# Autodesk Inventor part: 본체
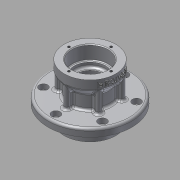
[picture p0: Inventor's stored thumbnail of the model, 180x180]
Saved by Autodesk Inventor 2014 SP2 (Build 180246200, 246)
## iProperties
Created: 2024-04
Part Number: 본체
Material: 알루미늄 6061
Document SubType Name: Modeling
Designer: Administrator
Density: 2.71 g/cm^3
Appearance: 알루미늄 - 평지
Mass: 492.903 g
Surface Area: 449.917 cm^2
Volume: 181.883 cm^3
Author: Administrator
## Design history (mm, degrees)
sketch "스케치1"
  geometry: L1 (-76.3, 0)-(76.3, 0) reference; L2 (0, -76.3)-(0, 76.3) reference; C1 r 54.5 at (0, 0); 1 further point
  constraints: 1 centre point, 1 coincident
  dimensions: "d0" = 109 diameter of C1
extrude "돌출1" new body sketch "스케치1" distance "d1" = 10; taper "d2" = 0 deg
sketch "스케치2"
  geometry: C1 r 54.5 at (0, 0) reference; C2 r 38.5 at (0, 0)
  constraints: 1 centre point, 1 coincident
  dimensions: "d3" = 77 diameter of C2
extrude "돌출2" join sketch "스케치2" distance "d4" = 5; taper "d5" = 0 deg
sketch "스케치3"
  geometry: C1 r 38.5 at (0, 0) reference; C2 r 33.5 at (0, 0)
  constraints: 1 centre point, 1 coincident
  dimensions: "d6" = 67 diameter of C2
extrude "돌출3" join sketch "스케치3" distance "d7" = 15; taper "d8" = 0 deg
node "작업 평면1"
sketch "스케치8"
  geometry: L1 (0, 0)-(0, 72.039); L2 (54.5, 10)-(-54.5, 10) reference; L3 (25.5, 10)-(25.5, 28.121); L4 (25.5, 28.121)-(33.5, 38); L5 (33.5, 38)-(33.5, 50); L6 (33.5, 50)-(0, 50); L7 (25.5, 10)-(0, 10); L8 (0, 50)-(0, 10)
  constraints: 14 end point, 2 perpendicular, 2 point on line, 1 collinear, 1 midpoint, 1 parallel, 1 vertical
  dimensions: "d21" = 67 diameter of L5.end L1; "d22" = 12 distance of L4.end L5.end; "d23" = 39 deg angle of L5 L4; "d24" = 40 distance from line of L3.start L6; "d25" = 51 diameter of L3 L1
revolve "회전1" sketch "스케치8" stored, may be unused: angle "d26" = 90 deg
node "작업 평면2"
sketch "스케치9"
  geometry: L1 (-76.3, 0)-(76.3, 0) reference; L2 (0, -76.3)-(0, 76.3) reference; L3 (0, 20.5)-(0, 30.5); L4 (3, 20.5)-(3, 30.5); L5 (-3, 30.5)-(-3, 20.5); L6 (-13.675, 33.5)-(11.062, 33.5); L7 (-16.254, 12.848)-(-24.914, 17.848); L8 (-27.914, 12.652)-(-19.254, 7.652); L9 (-19.254, -7.652)-(-27.914, -12.652); L10 (-24.914, -17.848)-(-16.254, -12.848); L11 (-3, -20.5)-(-3, -30.5); L12 (3, -30.5)-(3, -20.5); L13 (16.254, -12.848)-(24.914, -17.848); L14 (27.914, -12.652)-(19.254, -7.652); L15 (19.254, 7.652)-(27.914, 12.652); L16 (24.914, 17.848)-(16.254, 12.848); A1 r 3 centre (0, 20.5) between (-3, 20.5) and (3, 20.5); A2 r 3 centre (0, 30.5) between (3, 30.5) and (-3, 30.5); A3 r 3 centre (-26.414, 15.25) between (-24.914, 17.848) and (-27.914, 12.652); A4 r 3 centre (-17.754, 10.25) between (-19.254, 7.652) and (-16.254, 12.848); A5 r 3 centre (-26.414, -15.25) between (-27.914, -12.652) and (-24.914, -17.848); A6 r 3 centre (-17.754, -10.25) between (-16.254, -12.848) and (-19.254, -7.652); A7 r 3 centre (0, -30.5) between (-3, -30.5) and (3, -30.5); A8 r 3 centre (0, -20.5) between (3, -20.5) and (-3, -20.5); A9 r 3 centre (26.414, -15.25) between (24.914, -17.848) and (27.914, -12.652); A10 r 3 centre (17.754, -10.25) between (19.254, -7.652) and (16.254, -12.848); A11 r 3 centre (26.414, 15.25) between (27.914, 12.652) and (24.914, 17.848); A12 r 3 centre (17.754, 10.25) between (16.254, 12.848) and (19.254, 7.652); 3 further points
  constraints: 30 end point, 24 point on circle, 12 centre point, 5 tangent, 2 point on line, 1 midpoint, 1 parallel, 1 perpendicular, 1 vertical alignment, 62 other
  dimensions: "d36" = 6 diameter of A2; "d37" = 33.5 distance from line of point (0, 0) L6; "d40" = 360 deg dimension on point (0, 0) L4.start (derived)
extrude "돌출5" join sketch "스케치9" stored distance "d42" = 0; taper "d43" = 0 deg
extrude "돌출6" join sketch "스케치9" stored distance "d44" = 20; taper "d45" = 0 deg
sketch "스케치10"
  geometry: L1 (-33.5, -20)-(33.5, -20) reference; L2 (-33.5, 50)-(33.5, 50) reference; L3 (0, -34)-(0, 64) reference; L4 (23.5, 50)-(0, 50); L5 (0, 50)-(0, 32); L6 (0, 32)-(23.5, 32); L7 (23.5, 32)-(23.5, 50); L8 (20.5, 32)-(0, 32); L9 (0, 32)-(0, 26); L10 (0, 26)-(20.5, 26); L11 (20.5, 26)-(20.5, 32); L12 (16, 26)-(0, 26); L13 (0, 26)-(0, 4); L14 (0, 4)-(16, 4); L15 (16, 4)-(16, 26); L16 (0, 4)-(20.5, 4); L17 (20.5, 4)-(20.5, -2); L18 (20.5, -2)-(0, -2); L19 (0, -2)-(0, 4); L20 (0, -2)-(23.5, -2); L21 (23.5, -2)-(23.5, -20); L22 (23.5, -20)-(0, -20); L23 (0, -20)-(0, -2); 1 further point
  constraints: 40 end point, 10 parallel, 7 point on line, 5 horizontal, 5 perpendicular
  dimensions: "d46" = 47 diameter of L7 L3; "d47" = 18 distance of L6.end L4.start; "d48" = 41 diameter of L11 L3; "d49" = 6 distance of L10.end L8.start; "d50" = 32 diameter of L15 L3; "d51" = 22 distance of L14.end L12.start; "d52" = 41 diameter of L17 L3; "d53" = 6 distance of L16.end L17.end; "d54" = 47 diameter of L21 L3
revolve "회전2" sketch "스케치10" stored, may be unused: angle "d55" = 90 deg
fillet "모깎기1" dims "d56" = 3
fillet "모깎기2" dims "d57" = 3
fillet "모깎기3" dims "d58" = 3
chamfer "모따기1" distance "d59" = 1; stored, may be unused: second distance "d60" = 2, angle "d61" = 45 deg
fillet "모깎기4" dims "d62" = 3
chamfer "모따기2" distance "d63" = 1; stored, may be unused: second distance "d64" = 2, angle "d65" = 45 deg
fillet "모깎기5" dims "d66" = 3
fillet "모깎기6" dims "d67" = 1
fillet "모깎기7" dims "d68" = 3
sketch "스케치12"
  geometry: L1 (-76.3, 0)-(76.3, 0) reference; L2 (0, -76.3)-(0, 76.3) reference; C1 r 51.5 at (0, 0) reference; C2 r 5.5 at (0, 44.5); C3 r 5.5 at (-38.538, 22.25); C4 r 5.5 at (-38.538, -22.25); C5 r 5.5 at (0, -44.5); C6 r 5.5 at (38.538, -22.25); C7 r 5.5 at (38.538, 22.25); A1 r 25.5 centre (0, 0) between (24.273, -7.815) and (24.273, 7.815) reference
  constraints: 6 centre point, 1 point on line, 13 other
  dimensions: "d69" = 11 diameter of C2; "d70" = 44.5 distance of A1.centre C2.centre; "d73" = 360 deg dimension on C1.centre C2.centre (derived)
extrude "돌출7" cut sketch "스케치12" distance "d75" = 6.6; taper "d76" = 0 deg
sketch "스케치13"
  geometry: C1 r 5.5 at (0, 0) reference; C2 r 5.5 at (-38.538, 66.75) reference; C3 r 5.5 at (0, 44.5) reference; C4 r 5.5 at (-77.076, 44.5) reference; C5 r 5.5 at (-77.076, 0) reference; C6 r 5.5 at (-38.538, -22.25) reference; 7 further points
  constraints: 6 coincident
hole "구멍1" sketch "스케치13" at (-77.076, 44.5), (-77.076, 0), (-38.538, -22.25), (0, 0), (0, 44.5), (-38.538, 66.75) diameter "d77" = 6.6; stored, may be unused: countersink angle "d81" = 90 deg, drill point angle "d83" = 0 deg; dims "d78" = 6, "d79" = 4, "d80" = 2, "d82" = 8
sketch "스케치14"
  geometry: L1 (-76.3, 0)-(76.3, 0) reference; L2 (0, -76.3)-(0, 76.3) reference; 4 further points
  constraints: 4 point on line, 2 symmetric about line
  dimensions: "d84" = 55 distance of point (0, 27.5) point (0, -27.5); "d85" = 55 distance of point (-27.5, 0) point (27.5, 0)
hole "구멍2" sketch "스케치14" at (0, 27.5), (0, -27.5), (-27.5, 0), (27.5, 0) diameter "d86" = 3.242; stored, may be unused: countersink angle "d90" = 90 deg, drill point angle "d92" = 118 deg; dims "d87" = 8, "d88" = 4, "d89" = 2, "d91" = 10
sketch "스케치15"
  geometry: L1 (0, -76.3)-(0, 76.3) reference; L2 (76.3, 0)-(-76.3, 0) reference; 4 further points
  constraints: 4 point on line, 2 symmetric about line
  dimensions: "d93" = 55 distance of point (0, -27.5) point (0, 27.5); "d94" = 55 distance of point (-27.5, 0) point (27.5, 0)
hole "구멍3" sketch "스케치15" at (0, 27.5), (0, -27.5), (-27.5, 0), (27.5, 0) diameter "d95" = 3.242; stored, may be unused: countersink angle "d99" = 90 deg, drill point angle "d101" = 118 deg; dims "d96" = 8, "d97" = 4, "d98" = 2, "d100" = 10
node "작업 평면3"
sketch "스케치16"
  geometry: L1 (-33.5, 50)-(33.5, 50) reference; L2 (-76.3, 0)-(76.3, 0) reference; L3 (0, -34)-(0, 64) reference; 2 further points
  constraints: 1 point on line, 1 other
  dimensions: "d103" = 6 distance from line of L1 point (0, 44)
feature "엠보싱1" sketch "스케치16" dims "d0" = 109, "d21" = 67, "d22" = 12, "d23" = 39 deg, "d24" = 40, "d25" = 51, "d104" = 1, "d105" = 0
fillet "모깎기8" dims "d106" = 3
node "솔리드1"
node "투영된 루프2"
node "투영된 루프3"
node "투영된 루프4"
node "투영된 루프5"
node "투영된 루프6"
other parameters: "d27" = 8
